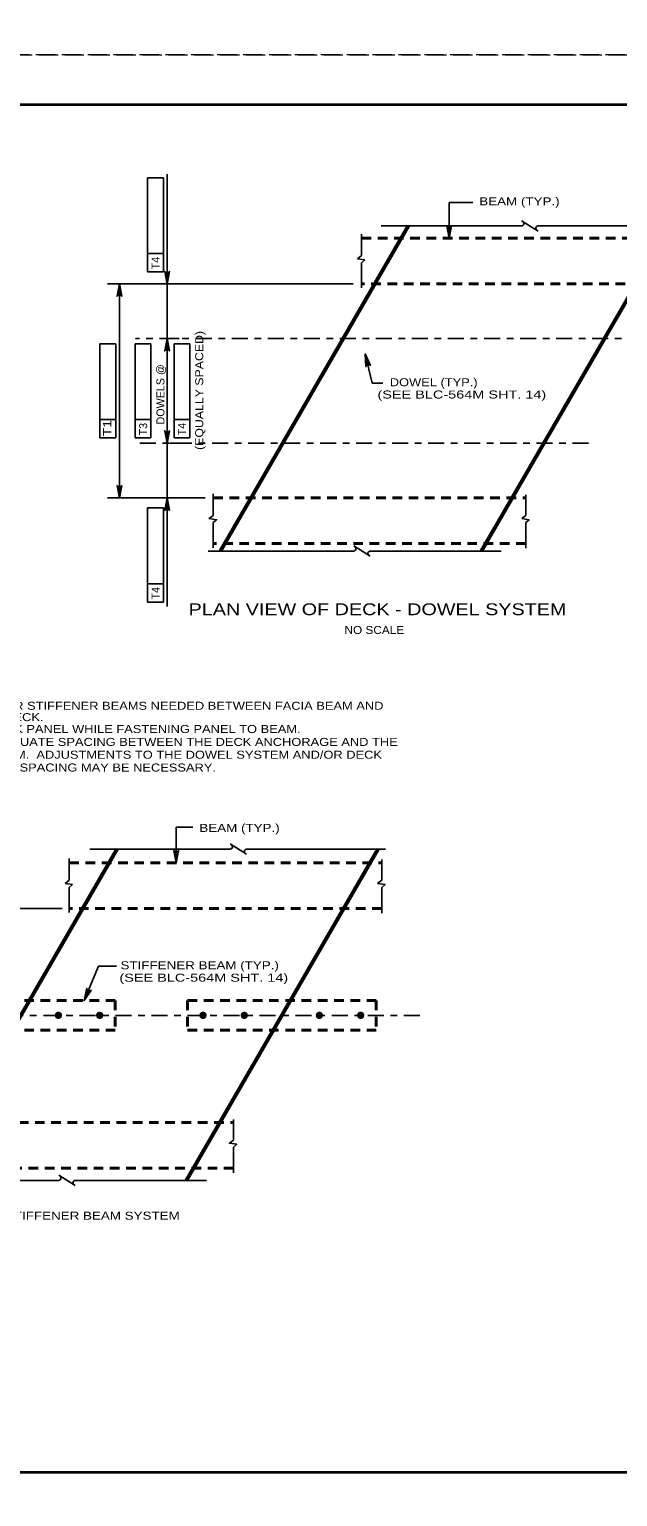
# Model space of a CAD drawing. Extents: x -11 to 79, y -154 to 0.
# Drawn here: x 50.93 to 59.74, y -87.62 to -65.62 of the extents above; entities that cross this region are included whole.
import ezdxf
from ezdxf.enums import TextEntityAlignment as Align

# ---------------------------------------------------------------- set-up
doc = ezdxf.new("R2010")
doc.units = 0
doc.header["$LTSCALE"] = 0.048
for name, pattern in [('DOT_DASHED', [7.7, 5, -1.2, 0.3, -1.2]), ('LONG_DASHED', [7.5, 6, -1.5]), ('MEDIUM_DASHED', [4.5, 3, -1.5])]:
    doc.linetypes.add(name, pattern=pattern)
for name, color, linetype, lineweight in [('1', 7, 'Continuous', 25), ('2', 7, 'Continuous', 35), ('3', 7, 'Continuous', 25), ('4', 7, 'Continuous', 25), ('63', 7, 'LONG_DASHED', 13)]:
    doc.layers.add(name, color=color, linetype=linetype, lineweight=lineweight)

msp = doc.modelspace()

# ---------------------------------------------------------------- hatches: boundary and pattern name
at = {"layer": '4'}
for points in [[(57.22058, -68.75025), (57.22183, -68.7455), (57.21942, -68.7455)], [(52.97317, -70.37483), (53.01317, -70.37483), (52.99317, -70.25483)], [(55.963, -70.48533), (55.96292, -70.49017), (55.96517, -70.48967)], [(53.13058, -78.11533), (53.13175, -78.11058), (53.12933, -78.11058)], [(51.749, -80.18225), (51.75192, -80.17833), (51.74975, -80.17742)]]:
    msp.add_hatch(color=256, dxfattribs=at).paths.add_polyline_path(points)

# ---------------------------------------------------------------- linework, layer by layer
at = {"layer": '1', "lineweight": 35}
msp.add_lwpolyline([(35.75, -87.25), (67.25, -87.25), (67.25, -66.75), (35.75, -66.75)], close=True, dxfattribs=at)
at = {"layer": '2', "lineweight": 53}
for p, q in [((56.60567, -68.56542), (53.7865, -73.44258)), ((60.51908, -68.56542), (57.69992, -73.44258)), ((52.23908, -77.90983), (49.36767, -82.87733)), ((56.15242, -77.90983), (53.28108, -82.87733))]:
    msp.add_line(p, q, dxfattribs=at)
at = {"layer": '3'}
for p, q in [((56.20075, -68.56542), (58.30225, -68.56542)), ((58.305, -68.488), (58.55142, -68.64283)), ((58.55083, -68.56542), (60.63383, -68.56542)), ((55.90517, -69.01167), (55.90517, -68.68775)), ((55.84358, -69.05925), (55.90517, -69.01167)), ((55.95392, -69.07625), (55.84358, -69.05925)), ((55.90517, -69.12), (55.95392, -69.07625)), ((55.90517, -69.49683), (55.90517, -69.12)), ((55.61283, -70.283), (55.64433, -70.2285)), ((54.70567, -71.85242), (54.73717, -71.79792)), ((53.685, -72.90658), (53.685, -72.58258)), ((58.36792, -72.90658), (58.36792, -72.59758)), ((58.30633, -72.95417), (58.36792, -72.90658)), ((58.41658, -72.97108), (58.30633, -72.95417)), ((53.60675, -73.44258), (55.78608, -73.44258)), ((55.78883, -73.36517), (56.03525, -73.52)), ((56.03467, -73.44258), (58.00075, -73.44258)), ((53.93842, -77.83242), (54.18475, -77.98725)), ((51.52667, -78.37675), (51.52667, -78.05283)), ((51.83408, -77.90983), (53.93558, -77.90983)), ((54.18425, -77.90983), (56.26717, -77.90983)), ((51.46508, -78.42433), (51.52667, -78.37675)), ((51.57533, -78.44133), (51.46508, -78.42433)), ((51.52667, -78.48508), (51.57533, -78.44133)), ((51.52667, -78.86192), (51.52667, -78.48508)), ((56.25825, -78.44133), (56.14792, -78.42433)), ((56.20958, -78.48508), (56.25825, -78.44133)), ((56.20958, -78.86942), (56.20958, -78.48508)), ((53.98917, -82.272), (53.98917, -81.963)), ((49.18792, -82.87733), (51.36725, -82.87733)), ((51.37, -82.79992), (51.61642, -82.95475)), ((51.61583, -82.87733), (53.58192, -82.87733))]:
    msp.add_line(p, q, dxfattribs=at)
at = {"layer": '3', "linetype": 'MEDIUM_DASHED', "lineweight": 40}
for p, q in [((55.90517, -68.75025), (60.58808, -68.75025)), ((60.58808, -69.43517), (55.90517, -69.43517)), ((53.685, -72.64508), (58.36792, -72.64508)), ((58.36792, -73.33008), (53.685, -73.33008)), ((51.52667, -78.11533), (56.20958, -78.11533)), ((56.20958, -78.80025), (51.52667, -78.80025)), ((49.39083, -80.18225), (52.21367, -80.18225)), ((52.21367, -80.18225), (52.21367, -80.62325)), ((53.30075, -80.18225), (53.30075, -80.62325)), ((49.39083, -80.62325), (52.21367, -80.62325)), ((53.30075, -80.62325), (56.12358, -80.62325)), ((49.30625, -82.0105), (53.98917, -82.0105)), ((53.98917, -82.6955), (49.30625, -82.6955))]:
    msp.add_line(p, q, dxfattribs=at)
at = {"layer": '3', "linetype": 'DOT_DASHED'}
for p, q in [((60.14133, -70.25575), (52.52025, -70.25458)), ((59.306, -71.82517), (52.51967, -71.824))]:
    msp.add_line(p, q, dxfattribs=at)
at = {"layer": '3'}
for points in [[(53.685, -73.39175), (53.685, -73.01483), (53.73375, -72.97108), (53.62342, -72.95417), (53.685, -72.90658)], [(58.36792, -73.39925), (58.36792, -73.01483), (58.41658, -72.97108)], [(56.14792, -78.42433), (56.20958, -78.37675), (56.20958, -78.06775)], [(53.98917, -82.76467), (53.98917, -82.38025), (54.03792, -82.3365), (53.92758, -82.3195), (53.98917, -82.272)]]:
    msp.add_lwpolyline(points, dxfattribs=at)
at = {"layer": '3', "linetype": 'MEDIUM_DASHED', "lineweight": 40}
msp.add_lwpolyline([(53.30075, -80.18225), (56.12358, -80.18225), (56.12358, -80.62325)], dxfattribs=at)
at = {"layer": '3', "lineweight": 40}
for centre, radius in [((51.36518, -80.40274), 0.03333), ((51.36518, -80.40274), 0.02953), ((51.36518, -80.40274), 0.025), ((51.36518, -80.40274), 0.01667), ((51.36518, -80.40274), 0.00833), ((51.98329, -80.40274), 0.03333), ((51.98329, -80.40274), 0.02953), ((51.98329, -80.40274), 0.025), ((51.98329, -80.40274), 0.01667), ((51.98329, -80.40274), 0.00833), ((53.53101, -80.40274), 0.03333), ((53.53101, -80.40274), 0.025), ((53.53101, -80.40274), 0.01667), ((53.53101, -80.40274), 0.00833), ((54.14912, -80.40274), 0.03333), ((54.14912, -80.40274), 0.025), ((54.14912, -80.40274), 0.01667), ((54.14912, -80.40274), 0.00833), ((55.2751, -80.40274), 0.03333), ((55.2751, -80.40274), 0.025), ((55.2751, -80.40274), 0.01667), ((55.2751, -80.40274), 0.00833), ((55.89321, -80.40274), 0.03333), ((55.89321, -80.40274), 0.025), ((55.89321, -80.40274), 0.01667), ((55.89321, -80.40274), 0.00833)]:
    msp.add_circle(centre, radius, dxfattribs=at)
at = {"layer": '3'}
for centre in [(53.53101, -80.40274), (54.14912, -80.40274), (55.2751, -80.40274), (55.89321, -80.40274)]:
    msp.add_circle(centre, 0.02953, dxfattribs=at)
for centre, start, end in [((58.30222, -68.52901), 270, 60), ((58.55424, -68.6016), 95.32859, 237.86724), ((55.78604, -73.4062), 270, 60), ((56.03806, -73.47878), 95.32859, 237.86724), ((53.93557, -77.87345), 270, 60), ((54.1876, -77.94604), 95.32859, 237.86724), ((51.36718, -82.84096), 270, 60), ((51.61921, -82.91354), 95.32859, 237.86724)]:
    msp.add_arc(centre, 0.03637, start, end, dxfattribs=at)
at = {"layer": '4'}
for p, q in [((52.70192, -67.84375), (52.93817, -67.84375)), ((52.70192, -68.98017), (52.70192, -67.84375)), ((52.93817, -67.84375), (52.93817, -69.25575)), ((52.99317, -69.19467), (52.99317, -67.79133)), ((57.22058, -68.75025), (57.22058, -68.21675)), ((57.22058, -68.21675), (57.57242, -68.21675)), ((52.70192, -69.25575), (52.70192, -68.98017)), ((52.93817, -68.98017), (52.70192, -68.98017)), ((52.93817, -69.25575), (52.70192, -69.25575)), ((52.99317, -70.25467), (52.99317, -69.19467)), ((55.783, -69.43517), (52.09783, -69.43517)), ((52.27783, -72.645), (52.27783, -69.43517)), ((52.93108, -69.43467), (52.81317, -69.43467)), ((51.98667, -70.33342), (52.22292, -70.33342)), ((51.98667, -71.46983), (51.98667, -70.33342)), ((52.22292, -70.33342), (52.22292, -71.74542)), ((52.51525, -71.74542), (52.51525, -70.33342)), ((52.51525, -70.33342), (52.75142, -70.33342)), ((52.75142, -70.33342), (52.75142, -71.74542)), ((52.99317, -71.82433), (52.99317, -70.25483)), ((52.99317, -70.37483), (52.99317, -70.49483)), ((53.03525, -70.25483), (53.17317, -70.25483)), ((53.09667, -70.33342), (53.33283, -70.33342)), ((53.09667, -71.46983), (53.09667, -70.33342)), ((53.33283, -70.33342), (53.33283, -71.74542)), ((55.963, -70.48533), (56.06625, -70.92408)), ((56.06625, -70.92408), (56.22708, -70.92408)), ((51.98667, -71.74542), (51.98667, -71.46983)), ((52.22292, -71.46983), (51.98667, -71.46983)), ((52.75142, -71.46983), (52.51525, -71.46983)), ((53.09667, -71.74542), (53.09667, -71.46983)), ((53.33283, -71.46983), (53.09667, -71.46983)), ((52.99317, -71.70433), (52.99317, -71.58433)), ((52.22292, -71.74542), (51.98667, -71.74542)), ((52.75142, -71.74542), (52.51525, -71.74542)), ((52.99317, -71.82425), (52.99317, -74.27242)), ((53.0345, -71.82425), (53.17317, -71.82425)), ((53.33283, -71.74542), (53.09667, -71.74542)), ((53.08725, -72.645), (52.09783, -72.645)), ((52.70192, -74.20625), (52.70192, -72.79417)), ((52.70192, -72.79417), (52.93817, -72.79417)), ((52.80617, -72.64483), (53.56483, -72.64508)), ((53.0475, -72.64492), (52.81317, -72.64492)), ((52.93817, -72.79417), (52.93817, -74.20625)), ((52.99317, -72.76492), (52.99317, -72.88492)), ((52.93817, -73.93058), (52.70192, -73.93058)), ((52.93817, -74.20625), (52.70192, -74.20625)), ((53.13058, -78.11533), (53.13058, -77.58183)), ((53.13058, -77.58183), (53.37933, -77.58183)), ((51.42308, -78.80025), (48.86583, -78.80025)), ((51.749, -80.18225), (51.96633, -79.66358)), ((51.96625, -79.66358), (52.23392, -79.66358))]:
    msp.add_line(p, q, dxfattribs=at)
at = {"layer": '4', "linetype": 'DOT_DASHED'}
msp.add_line((49.51892, -80.40275), (56.81008, -80.40275), dxfattribs=at)
at = {"layer": '4'}
for points in [[(57.22058, -68.75025), (57.18567, -68.56383), (57.19558, -68.57817), (57.20808, -68.58558), (57.22058, -68.58775), (57.23308, -68.58558), (57.24558, -68.57817), (57.2555, -68.56383), (57.22058, -68.75025), (57.24558, -68.57817), (57.23308, -68.58558), (57.22058, -68.75025), (57.22058, -68.58775), (57.20808, -68.58558), (57.22058, -68.75025), (57.19558, -68.57817)], [(52.99317, -69.43517), (52.95825, -69.24875), (52.96817, -69.26308), (52.98067, -69.2705), (52.99317, -69.27267), (53.00567, -69.2705), (53.01817, -69.26308), (53.02808, -69.24875), (52.99317, -69.43517), (53.01817, -69.26308), (53.00567, -69.2705), (52.99317, -69.43517), (52.99317, -69.27267), (52.98067, -69.2705), (52.99317, -69.43517), (52.96817, -69.26308)], [(52.27783, -69.43517), (52.31275, -69.62158), (52.30283, -69.60725), (52.29033, -69.59983), (52.27783, -69.59767), (52.26533, -69.59983), (52.25283, -69.60725), (52.24292, -69.62158), (52.27783, -69.43517), (52.25283, -69.60725), (52.26533, -69.59983), (52.27783, -69.43517), (52.27783, -69.59767), (52.29033, -69.59983), (52.27783, -69.43517), (52.30283, -69.60725)], [(52.99317, -70.25467), (53.02808, -70.44108), (53.01817, -70.42667), (53.00567, -70.41933), (52.99317, -70.41717), (52.98067, -70.41933), (52.96817, -70.42667), (52.95825, -70.44108), (52.99317, -70.25467), (52.96817, -70.42667), (52.98067, -70.41933), (52.99317, -70.25467), (52.99317, -70.41717), (53.00567, -70.41933), (52.99317, -70.25467), (53.01817, -70.42667)], [(55.963, -70.48533), (56.03975, -70.65875), (56.02675, -70.64708), (56.01292, -70.64275), (56.00025, -70.6435), (55.98858, -70.6485), (55.97808, -70.6585), (55.97167, -70.67483), (55.963, -70.48533), (55.97808, -70.6585), (55.98858, -70.6485), (55.963, -70.48533), (56.00025, -70.6435), (56.01292, -70.64275), (55.963, -70.48533), (56.02675, -70.64708)], [(52.99317, -71.82408), (52.95825, -71.63767), (52.96817, -71.652), (52.98067, -71.65942), (52.99317, -71.66158), (53.00567, -71.65942), (53.01817, -71.652), (53.02808, -71.63767), (52.99317, -71.82408), (53.01817, -71.652), (53.00567, -71.65942), (52.99317, -71.82408), (52.99317, -71.66158), (52.98067, -71.65942), (52.99317, -71.82408), (52.96817, -71.652)], [(52.27783, -72.645), (52.24292, -72.45858), (52.25283, -72.47292), (52.26533, -72.48033), (52.27783, -72.4825), (52.29033, -72.48033), (52.30283, -72.47292), (52.31275, -72.45858), (52.27783, -72.645), (52.30283, -72.47292), (52.29033, -72.48033), (52.27783, -72.645), (52.27783, -72.4825), (52.26533, -72.48033), (52.27783, -72.645), (52.25283, -72.47292)], [(52.99317, -72.64492), (53.02808, -72.83133), (53.01817, -72.81692), (53.00567, -72.8095), (52.99317, -72.80742), (52.98067, -72.8095), (52.96817, -72.81692), (52.95825, -72.83133), (52.99317, -72.64492), (52.96817, -72.81692), (52.98067, -72.8095), (52.99317, -72.64492), (52.99317, -72.80742), (53.00567, -72.8095), (52.99317, -72.64492), (53.01817, -72.81692)], [(53.13058, -78.11533), (53.09567, -77.92892), (53.10558, -77.94325), (53.11808, -77.95067), (53.13058, -77.95283), (53.14308, -77.95067), (53.15558, -77.94325), (53.1655, -77.92892), (53.13058, -78.11533), (53.15558, -77.94325), (53.14308, -77.95067), (53.13058, -78.11533), (53.13058, -77.95283), (53.11808, -77.95067), (53.13058, -78.11533), (53.10558, -77.94325)], [(51.749, -80.18225), (51.78883, -79.99683), (51.79242, -80.01392), (51.80108, -80.02558), (51.81183, -80.03242), (51.82417, -80.03525), (51.83858, -80.03325), (51.85325, -80.02383), (51.749, -80.18225), (51.83858, -80.03325), (51.82417, -80.03525), (51.749, -80.18225), (51.81183, -80.03242), (51.80108, -80.02558), (51.749, -80.18225), (51.79242, -80.01392)]]:
    msp.add_lwpolyline(points, dxfattribs=at)
for points in [[(57.22058, -68.75025), (57.22183, -68.7455), (57.21942, -68.7455)], [(52.97317, -70.37483), (53.01317, -70.37483), (52.99317, -70.25483)], [(55.963, -70.48533), (55.96292, -70.49017), (55.96517, -70.48967)], [(53.13058, -78.11533), (53.13175, -78.11058), (53.12933, -78.11058)], [(51.749, -80.18225), (51.75192, -80.17833), (51.74975, -80.17742)]]:
    msp.add_lwpolyline(points, close=True, dxfattribs=at)
at = {"layer": '63'}
for points in [[(34, -66), (68, -66), (68, -44), (34, -44)], [(34, -88), (68, -88), (68, -66), (34, -66)]]:
    msp.add_lwpolyline(points, close=True, dxfattribs=at)

# ---------------------------------------------------------------- texts
at = {"layer": '4'}
for s, width, p in [('BEAM (TYP.)', 1.25, (57.67042, -68.25792)), ('(SEE BLC-564M SHT. 14)', 1.35, (56.145, -71.15417)), ('DOWEL (TYP.)', 1.2, (56.33008, -70.97033)), ('NO SCALE', 1.1, (55.65167, -74.68467)), ('OUTSIDE OF DECK.', 1.2, (49.32283, -75.991)), ('NO DOWELS OR STIFFENER BEAMS NEEDED BETWEEN FACIA BEAM AND ', 1.2, (49.32283, -75.821)), ('PRELOAD DECK PANEL WHILE FASTENING PANEL TO BEAM.', 1.2, (49.32283, -76.16908)), ('PROVIDE ADEQUATE SPACING BETWEEN THE DECK ANCHORAGE AND THE ', 1.2, (49.32283, -76.363)), ('DOWEL SYSTEM.  ADJUSTMENTS TO THE DOWEL SYSTEM AND/OR DECK', 1.2, (49.32283, -76.55492)), ("ANCHORAGE'S SPACING MAY BE NECESSARY.", 1.2, (49.32283, -76.74683)), ('BEAM (TYP.)', 1.25, (53.47667, -77.65242)), ('STIFFENER BEAM (TYP.)', 1.25, (52.29475, -79.71208)), ('(SEE BLC-564M SHT. 14)', 1.35, (52.27867, -79.89817))]:
    msp.add_text(s, height=0.12, dxfattribs=dict(at, width=width)).set_placement(p)
for s, p in [('T4', (52.881, -69.12329)), ('DOWELS @', (52.95317, -71.09125)), ('T3', (52.69425, -71.61321)), ('T4', (53.27567, -71.61296)), ('T4', (52.881, -74.07379))]:
    msp.add_text(s, height=0.12, rotation=90, dxfattribs=at).set_placement(p, align=Align.CENTER)
for s, width, p in [('(EQUALLY SPACED)', 1.15, (53.53458, -71.03329)), ('T1', 1.3, (52.15525, -71.59887))]:
    msp.add_text(s, height=0.12, rotation=90, dxfattribs=dict(at, width=width)).set_placement(p, align=Align.CENTER)
at = {"layer": '4', "width": 1.25}
for s, height, p in [('PLAN VIEW OF DECK - DOWEL SYSTEM', 0.1772, (56.14583, -74.40258)), ('SINGLE (1) STIFFENER BEAM SYSTEM', 0.12, (51.32725, -83.46667))]:
    msp.add_text(s, height=height, dxfattribs=at).set_placement(p, align=Align.CENTER)

doc.saveas('drawing.dxf')
